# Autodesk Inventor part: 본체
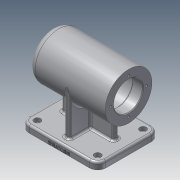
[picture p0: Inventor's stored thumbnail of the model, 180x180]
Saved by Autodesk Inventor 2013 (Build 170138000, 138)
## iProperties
Created: 2020-10
Part Number: 본체
Material: 알루미늄 6061
Document SubType Name: Modeling
Designer: user
Density: 1 g/cm^3
Author: user
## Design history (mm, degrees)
sketch "스케치1"
  geometry: C1 r 34 at (0, 0); 1 further point
  constraints: 1 centre point, 1 coincident
  dimensions: "d0" = 68 diameter of C1
extrude "돌출1" new body sketch "스케치1" distance "d1" = 112; taper "d2" = 0 deg
node "작업 평면1"
sketch "스케치2"
  geometry: L1 (45, 112)-(-45, 112); L2 (-45, 112)-(-45, 0); L3 (-45, 0)-(45, 0); L4 (45, 0)-(45, 112); L5 (45, 112)-(-45, 0); L6 (-45, 112)-(45, 0); 3 further points
  constraints: 12 end point, 3 midpoint, 2 parallel, 1 coincident, 1 horizontal, 1 perpendicular
  dimensions: "d4" = 90 distance of L3.end L2.end; "d5" = 112 distance of L2.end L1.end
extrude "돌출2" join sketch "스케치2" distance "d6" = 10; taper "d7" = 0 deg
sketch "스케치3"
  geometry: L1 (-45, -112)-(45, -112) reference; L2 (45, 0)-(-45, 0) reference; L3 (-45, 0)-(-45, -112) reference; L4 (-4, -94)-(4, -94); L5 (4, -94)-(4, -18); L6 (4, -18)-(-4, -18); L7 (-4, -18)-(-4, -94); L8 (-4, -94)-(4, -18); L9 (4, -94)-(-4, -18); 2 further points
  constraints: 12 end point, 2 midpoint, 2 parallel, 1 horizontal, 1 perpendicular
  dimensions: "d8" = 8 distance of L5.end L6.end; "d10" = 18 distance between parallel lines of L2 L6; "d11" = 18 distance between parallel lines of L1 L4; "d12" = 45 distance from line of point (0, -56) L3
extrude "돌출3" join sketch "스케치3" stored distance "d13" = 10; taper "d14" = 0 deg
sketch "스케치4"
  geometry: L1 (45, 0)-(-45, 0) reference; L2 (-34, -52)-(34, -52); L3 (34, -52)-(34, -60); L4 (34, -60)-(-34, -60); L5 (-34, -60)-(-34, -52); L6 (-34, -52)-(34, -60); L7 (34, -52)-(-34, -60); 4 further points
  constraints: 12 end point, 4 midpoint, 2 parallel, 1 horizontal, 1 perpendicular, 1 vertical alignment
  dimensions: "d15" = 8 distance of L4.end L2.start; "d17" = 68 distance of L3.end L4.end; "d18" = 56 distance from line of L1 point (0, -56)
extrude "돌출4" join sketch "스케치4" stored distance "d19" = 10; taper "d20" = 0 deg
sketch "스케치5"
  geometry: L1 (34, 112)-(34, 0) reference; L2 (34, 0)-(-34, 0) reference; L3 (-34, 0)-(-34, 18) reference; L4 (-34, 18)-(-64, 18) reference; L5 (-64, 18)-(-64, 0) reference; L6 (-64, 0)-(-74, 0) reference; L7 (-74, 0)-(-74, 112) reference; L8 (-74, 112)-(-64, 112) reference; L9 (-64, 112)-(-64, 94) reference; L10 (-64, 94)-(-34, 94) reference; L11 (-34, 94)-(-34, 112) reference; L12 (-34, 112)-(34, 112) reference; L13 (0, 112)-(0, 0); L14 (0, 0)-(21, 0); L15 (21, 0)-(21, 15); L16 (21, 15)-(24, 15); L17 (24, 15)-(24, 69); L18 (24, 69)-(21, 69); L19 (21, 69)-(21, 81); L20 (21, 81)-(17.5, 81); L21 (17.5, 81)-(17.5, 99); L22 (17.5, 99)-(16, 99); L23 (16, 99)-(16, 103); L24 (16, 103)-(10.5, 103); L25 (10.5, 103)-(10.5, 106); L26 (10.5, 106)-(0, 106)
  constraints: 28 end point, 8 parallel, 4 perpendicular, 2 point on line, 1 collinear, 1 midpoint
  dimensions: "d21" = 15 distance of L14.end L15.end; "d23" = 54 distance of L16.end L17.end; "d24" = 12 distance of L18.end L19.end; "d25" = 18 distance of L20.end L21.end; "d26" = 4 distance of L22.end L23.end; "d27" = 3 distance of L24.end L25.end; "d28" = 42 diameter of L15 L13; "d29" = 48 diameter of L17 L13; "d30" = 42 diameter of L19 L13; "d31" = 35 diameter of L21 L13; "d32" = 32 diameter of L23 L13; "d33" = 21 diameter of L25 L13
revolve "회전1" sketch "스케치5" stored, may be unused: angle "d34" = 90 deg
fillet "모깎기1" dims "d35" = 3
fillet "모깎기2" dims "d36" = 0.3
fillet "모깎기3" dims "d37" = 3
chamfer "모따기1" distance "d38" = 1; stored, may be unused: second distance "d39" = 2, angle "d40" = 45 deg
sketch "스케치6" dims "d41" = 52
  geometry: C1 r 34 at (0, 0) reference; C2 r 22 at (0, 0) reference; 2 further points
  constraints: 3 coincident, 2 vertical alignment, 2 other
hole "구멍1" sketch "스케치6" at (0, 26) diameter "d42" = 3.242; stored, may be unused: countersink angle "d46" = 90 deg, drill point angle "d48" = 118 deg; dims "d43" = 8, "d44" = 4, "d45" = 2, "d47" = 11
sketch "스케치7"
  geometry: L1 (0, 0)-(112, 0) reference; L2 (112, 0)-(112, 10) reference; 2 further points
  constraints: 1 other
  dimensions: "d52" = 56 distance from line of L2 point (56, 3); "d53" = 3 distance from line of L1 point (56, 3)
feature "엠보싱1" sketch "스케치7" dims "d1" = 112, "d2" = 0, "d54" = 0.5, "d55" = 0
fillet "모깎기4" dims "d56" = 12
sketch "스케치8"
  geometry: A1 r 12 centre (-33, -100) between (-45, -100) and (-33, -112) reference; A2 r 12 centre (33, -100) between (33, -112) and (45, -100) reference; A3 r 12 centre (33, -12) between (45, -12) and (33, 0) reference; A4 r 12 centre (-33, -12) between (-33, 0) and (-45, -12) reference; 5 further points
  constraints: 4 coincident
hole "구멍2" sketch "스케치8" at (-33, -100), (33, -100), (33, -12), (-33, -12) diameter "d57" = 5.5; stored, may be unused: countersink angle "d61" = 90 deg, drill point angle "d63" = 118 deg; dims "d58" = 8, "d59" = 9.5, "d60" = 5.4, "d62" = 11
fillet "모깎기5" dims "d64" = 10
fillet "모깎기6" dims "d65" = 3
fillet "모깎기7" dims "d66" = 3
fillet "모깎기8" dims "d67" = 3
fillet "모깎기9" dims "d68" = 3
fillet "모깎기10" dims "d69" = 3
node "솔리드1"
pattern_circular "원형 패턴1" dims angle "d50" = 360 deg
node "절단 모서리 투영1"
other parameters: "d3" = -74
